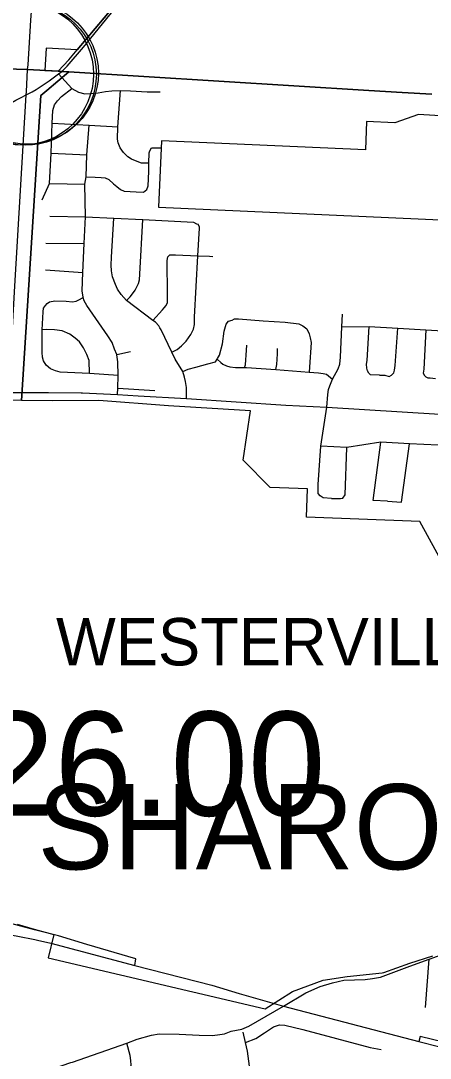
# Model space of a CAD drawing. Extents: x 1659811 to 1934326, y 644115 to 934867.
# Drawn here: x 1836578 to 1840906, y 767513 to 778471 of the extents above; entities that cross this region are included whole.
import ezdxf

# ---------------------------------------------------------------- set-up
doc = ezdxf.new("R2010")
doc.units = 0
for name, color, linetype in [('Default', 7, 'Continuous'), ('GM_X_City_Street', 7, 'Continuous'), ('GM_X_Corporation', 7, 'Continuous'), ('GM_X_Corporation_Text', 7, 'Continuous'), ('GM_X_County', 7, 'Continuous'), ('GM_X_Interchange_Ramps', 7, 'Continuous'), ('GM_X_Interstate_Route', 7, 'Continuous'), ('GM_X_State_Route', 7, 'Continuous'), ('GM_X_Township_Text', 7, 'Continuous')]:
    doc.layers.add(name, color=color, linetype=linetype)

msp = doc.modelspace()

# ---------------------------------------------------------------- linework, layer by layer
at = {"layer": 'Default'}
for centre in [(1836597, 777908), (1836627, 777906), (1836649, 777917)]:
    msp.add_circle(centre, 750, dxfattribs=at)
at = {"layer": 'GM_X_City_Street'}
for points in [[(1837011, 777935), (1837067, 777991), (1837241, 778192), (1837519, 778532), (1837662, 778703)], [(1834310, 774706), (1834473, 774909), (1834923, 775441), (1835241, 775829), (1835846, 776555), (1835996, 776796), (1836045, 776931), (1836080, 777037), (1836175, 777274), (1836350, 777500), (1836418, 777561), (1836459, 777592), (1836482, 777608), (1836525, 777633), (1836582, 777661), (1836636, 777689), (1836698, 777721), (1836741, 777744), (1836879, 777837), (1836977, 777910), (1837011, 777935)], [(1836977, 777910), (1837119, 777755), (1837190, 777715), (1837255, 777700), (1837313, 777701), (1837396, 777711), (1837474, 777725), (1837541, 777730), (1837631, 777735), (1837738, 777730), (1837914, 777719), (1837930, 777719)], [(1836806, 776578), (1836882, 776753), (1836901, 777072), (1836909, 777391), (1836918, 777522), (1836935, 777584), (1836967, 777626), (1837010, 777672), (1837119, 777755)], [(1837932, 776968), (1837854, 776968), (1837792, 776991), (1837748, 777008), (1837708, 777034), (1837665, 777079), (1837628, 777130), (1837608, 777180), (1837602, 777219), (1837603, 777351), (1837631, 777735)], [(1837930, 777719), (1838052, 777719)], [(1836909, 777391), (1837300, 777367), (1837603, 777351)], [(1837601, 774525), (1837603, 774592), (1837607, 774724), (1837604, 774867), (1837595, 774941), (1837592, 774947), (1837569, 775003), (1837544, 775072), (1837499, 775144), (1837276, 775465), (1837248, 775514), (1837239, 775547), (1837237, 775556), (1837227, 775614), (1837229, 775716), (1837234, 775812), (1837249, 776118), (1837263, 776400), (1837257, 776745), (1837268, 776821), (1837278, 777054), (1837300, 777367)], [(1837268, 776821), (1837364, 776818), (1837429, 776816), (1837470, 776812), (1837509, 776793), (1837559, 776750), (1837594, 776721), (1837632, 776687), (1837672, 776672), (1837799, 776663), (1837875, 776662), (1837910, 776688), (1837924, 776726), (1837931, 776878), (1837932, 776968), (1837936, 777075), (1837943, 777098), (1837959, 777128), (1838019, 777128), (1838066, 777129)], [(1836901, 777072), (1837278, 777054)], [(1836882, 776753), (1837257, 776745)], [(1836884, 776407), (1837263, 776400)], [(1837263, 776400), (1837562, 776386), (1837868, 776371), (1838405, 776345), (1838436, 776327), (1838454, 776322)], [(1838330, 774482), (1838331, 774598), (1838320, 774662), (1838310, 774707), (1838291, 774765), (1838209, 774896), (1838174, 774969), (1838061, 775206), (1838047, 775226), (1838036, 775248), (1838002, 775287), (1837973, 775306), (1837694, 775517), (1837638, 775579), (1837601, 775636), (1837580, 775684), (1837549, 775766), (1837538, 775829), (1837534, 775889), (1837537, 775973), (1837562, 776386)], [(1837694, 775517), (1837736, 775556), (1837768, 775600), (1837789, 775627), (1837811, 775673), (1837822, 775695), (1837832, 775735), (1837835, 775795), (1837868, 776371)], [(1838174, 774969), (1838230, 774998), (1838277, 775037), (1838327, 775085), (1838374, 775158), (1838403, 775212), (1838413, 775262), (1838414, 775340), (1838451, 775989), (1838468, 776280), (1838468, 776292), (1838454, 776322)], [(1836844, 776121), (1837249, 776118)], [(1837973, 775306), (1838077, 775418), (1838095, 775438), (1838114, 775462), (1838129, 775495), (1838129, 775578), (1838127, 775937), (1838133, 775979), (1838152, 775997), (1838214, 776000), (1838451, 775989), (1838572, 775984), (1838607, 775982)], [(1836839, 775841), (1837234, 775812)], [(1837607, 774724), (1837303, 774744), (1836994, 774761), (1836944, 774772), (1836891, 774796), (1836848, 774834), (1836817, 774880), (1836809, 774918), (1836806, 774968), (1836805, 775173), (1836806, 775208), (1836815, 775395), (1836820, 775437), (1836840, 775464), (1836856, 775486), (1836883, 775502), (1836939, 775513), (1837058, 775508), (1837126, 775503), (1837164, 775509), (1837192, 775524), (1837239, 775547)], [(1838291, 774765), (1838346, 774792), (1838428, 774813), (1838556, 774846), (1838638, 774869), (1838654, 774896), (1838658, 774903), (1838679, 774940), (1838710, 775060), (1838728, 775194), (1838749, 775268), (1838775, 775298), (1838811, 775307), (1838837, 775321), (1838881, 775322), (1839141, 775303), (1839372, 775289), (1839516, 775269), (1839561, 775248), (1839603, 775216), (1839628, 775164), (1839638, 775121), (1839649, 775073), (1839630, 774811), (1839625, 774760)], [(1839814, 774390), (1839822, 774523), (1839830, 774577), (1839844, 774616), (1839872, 774686), (1839933, 774796), (1839950, 774844), (1839957, 774916), (1839970, 775238), (1839979, 775371)], [(1839970, 775238), (1840262, 775243), (1840564, 775225), (1840861, 775207), (1841162, 775189), (1841222, 775185), (1841290, 775172), (1841353, 775141), (1841397, 775101), (1841404, 775090), (1841428, 775058), (1841443, 775004), (1841449, 774946), (1841435, 774301)], [(1840368, 774727), (1840274, 774732), (1840258, 774748), (1840242, 774772), (1840235, 774800), (1840233, 774844), (1840238, 774882), (1840262, 775243)], [(1840368, 774727), (1840425, 774728), (1840471, 774713), (1840497, 774729), (1840520, 774753), (1840530, 774781), (1840535, 774829), (1840564, 775225)], [(1837303, 774744), (1837300, 774882), (1837275, 774947), (1837242, 775015), (1837199, 775080), (1837153, 775120), (1837096, 775159), (1837015, 775196), (1836933, 775207), (1836853, 775210), (1836806, 775208)], [(1840861, 775207), (1840838, 774791), (1840833, 774747), (1840847, 774725), (1840861, 774709), (1840880, 774698), (1840904, 774698), (1840962, 774691)], [(1838943, 774809), (1838953, 774838), (1838965, 774992), (1838969, 775044)], [(1839275, 774786), (1839284, 774840), (1839290, 774953), (1839293, 775010)], [(1837592, 774947), (1837737, 774979)], [(1838654, 774896), (1838692, 774862), (1838714, 774844), (1838753, 774827), (1838787, 774817), (1838847, 774810), (1838943, 774809), (1838963, 774809), (1839275, 774786), (1839625, 774760), (1839725, 774752), (1839773, 774745), (1839809, 774739), (1839872, 774686)], [(1837603, 774592), (1837995, 774566)], [(1836002, 774546), (1836377, 774544), (1836453, 774543), (1836582, 774543)], [(1836582, 774543), (1836871, 774544), (1837216, 774542)], [(1837216, 774542), (1837230, 774542), (1837601, 774525), (1837819, 774511), (1838330, 774482), (1839378, 774411), (1839814, 774390), (1841008, 774316), (1841435, 774301), (1842324, 774250), (1842611, 774230), (1843171, 774207)], [(1839862, 773424), (1839776, 773432), (1839744, 773453), (1839722, 773479), (1839721, 773573), (1839748, 773976), (1839814, 774390)], [(1841982, 772844), (1841774, 773225), (1841588, 773468), (1841569, 773501), (1841526, 773670), (1841466, 773770), (1841395, 773838), (1841292, 773914), (1841196, 773956), (1841148, 773969), (1840991, 773988), (1840688, 774003), (1840385, 774021), (1840025, 773963), (1839748, 773976)], [(1840454, 773397), (1840304, 773402), (1840385, 774021)], [(1839862, 773424), (1839958, 773424), (1839982, 773428), (1840006, 773464), (1840025, 773963)], [(1840454, 773397), (1840602, 773387), (1840688, 774003)], [(1840855, 768049), (1840896, 768559)], [(1838994, 767428), (1838974, 767586), (1838953, 767678), (1838929, 767787)], [(1838953, 767678), (1839062, 767722), (1839154, 767782), (1839248, 767843), (1839314, 767865), (1839370, 767863), (1839561, 767816), (1840270, 767627), (1840386, 767604)], [(1837794, 767098), (1837738, 767268), (1837724, 767364), (1837745, 767439), (1837743, 767487), (1837735, 767541), (1837700, 767671)]]:
    msp.add_lwpolyline(points, dxfattribs=at)
at = {"layer": 'GM_X_Corporation'}
for points in [[(1837650, 778732), (1837174, 778163), (1836848, 778182), (1836833, 777945), (1836973, 777937), (1837085, 777931), (1836852, 777733), (1836789, 777680), (1836587, 774459), (1836117, 774478)], [(1841326, 772218), (1840796, 773182), (1839597, 773227), (1839608, 773527), (1839213, 773542), (1838929, 773828), (1839006, 774350), (1838141, 774402), (1837403, 774461), (1836916, 774455), (1836587, 774459), (1836789, 777680), (1836852, 777733), (1837085, 777931), (1836973, 777937), (1836974, 777938), (1837086, 778057), (1837174, 778163), (1837650, 778732)], [(1836540, 768927), (1836720, 768876), (1836928, 768819), (1836866, 768573), (1839160, 768034), (1839449, 768218), (1839773, 768339), (1840029, 768377), (1840398, 768414), (1840415, 768417), (1840690, 768517), (1840933, 768594)]]:
    msp.add_lwpolyline(points, dxfattribs=at)
msp.add_lwpolyline([(1838033, 776502), (1842974, 776280), (1842842, 776467), (1842767, 776576), (1842710, 776732), (1842648, 776896), (1842594, 777087), (1842556, 777259), (1842523, 777374), (1840783, 777481), (1840533, 777392), (1840233, 777406), (1840220, 777106), (1838064, 777201)], close=True, dxfattribs=at)
at = {"layer": 'GM_X_County'}
for points in [[(1827947, 778461), (1830981, 778275), (1835717, 778005), (1835956, 777979), (1836651, 777955), (1836973, 777937), (1837011, 777935), (1837085, 777931), (1840257, 777736), (1840611, 777712), (1840924, 777694)], [(1840924, 777694), (1840611, 777712), (1840257, 777736), (1837085, 777931), (1837011, 777935), (1836973, 777937), (1836651, 777955), (1835956, 777979), (1835717, 778005), (1830981, 778275), (1827947, 778461)]]:
    msp.add_lwpolyline(points, dxfattribs=at)
at = {"layer": 'GM_X_Interchange_Ramps'}
for points in [[(1837785, 768493), (1837796, 768562), (1837278, 768713), (1836978, 768804), (1836722, 768870), (1836271, 768989)], [(1844491, 766721), (1844503, 766768), (1844160, 766860), (1842937, 767186), (1842750, 767236), (1841408, 767595), (1840801, 767742), (1840787, 767690)]]:
    msp.add_lwpolyline(points, dxfattribs=at)
at = {"layer": 'GM_X_Interstate_Route'}
for points in [[(1836655, 778007), (1836686, 778478), (1836705, 778752)], [(1836445, 774439), (1836453, 774543), (1836516, 775666), (1836636, 777689), (1836638, 777722), (1836651, 777955)], [(1836651, 777955), (1836655, 778007)], [(1836265, 768858), (1836453, 768820), (1836546, 768801), (1836726, 768767), (1836755, 768760)], [(1836755, 768760), (1836897, 768727), (1837785, 768493), (1838596, 768283), (1838886, 768198)], [(1838886, 768198), (1839355, 768061)], [(1839355, 768061), (1840787, 767690)], [(1840787, 767690), (1841008, 767632)]]:
    msp.add_lwpolyline(points, dxfattribs=at)
at = {"layer": 'GM_X_State_Route'}
for points in [[(1838658, 767760), (1838732, 767772), (1838801, 767797), (1838915, 767820), (1838989, 767851), (1839355, 768061), (1839591, 768205), (1839743, 768271), (1839874, 768308), (1839991, 768337), (1840219, 768345), (1840296, 768354), (1840382, 768368), (1840465, 768400), (1840690, 768485), (1840896, 768559), (1841120, 768639), (1841502, 768772), (1842103, 768904), (1842233, 768930), (1842548, 768991), (1842858, 769056)], [(1834864, 767195), (1835230, 767180), (1835747, 767150), (1835961, 767138), (1836027, 767139), (1836095, 767144), (1836153, 767154), (1836296, 767188), (1837108, 767466), (1837126, 767472), (1837700, 767671), (1837808, 767714), (1837959, 767757), (1838042, 767769), (1838253, 767766), (1838464, 767757), (1838601, 767752), (1838658, 767760)]]:
    msp.add_lwpolyline(points, dxfattribs=at)

# ---------------------------------------------------------------- texts
at = {"layer": 'Default'}
msp.add_text('26.00', height=1100, dxfattribs=at).set_placement((1836117, 770074))
at = {"layer": 'GM_X_Corporation_Text'}
msp.add_text('WESTERVILLE', height=500, rotation=0, dxfattribs=at).set_placement((1836951, 771662))
at = {"layer": 'GM_X_Township_Text'}
msp.add_text('SHARON', height=900, rotation=0, dxfattribs=at).set_placement((1836755, 769508))

doc.saveas('drawing.dxf')
